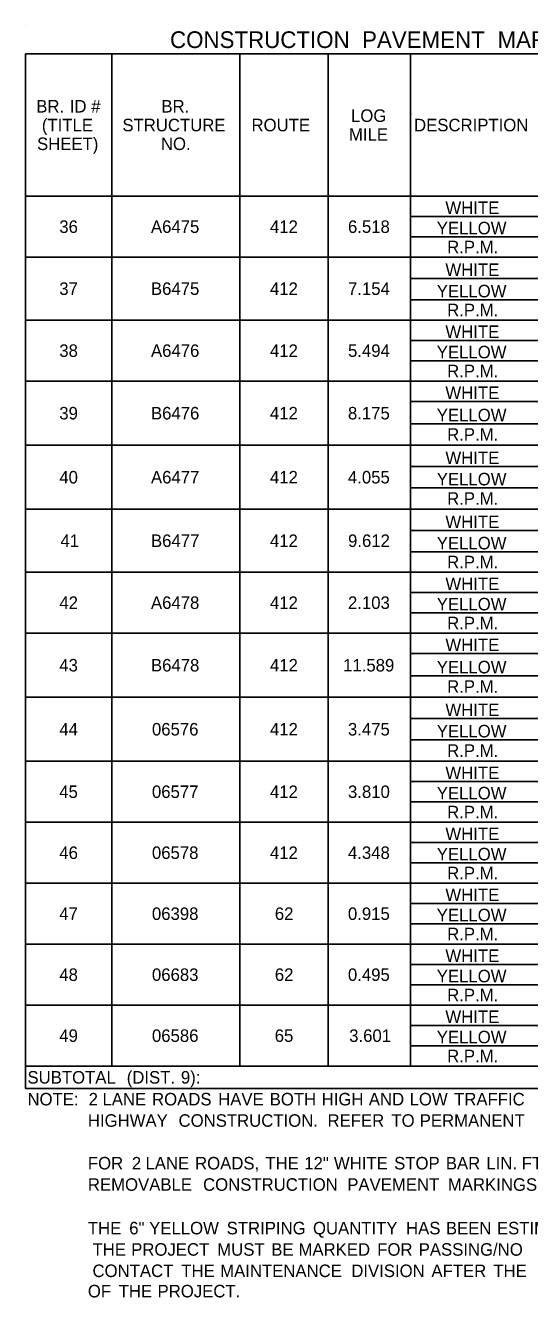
# Model space of a CAD drawing. Extents: x 544420 to 1930787, y -1947044 to 596640.
# Drawn here: x 549970 to 550212, y -1946848 to -1946238 of the extents above; entities that cross this region are included whole.
import ezdxf

# ---------------------------------------------------------------- set-up
doc = ezdxf.new("R2010")
doc.units = 0
doc.layers.add('Default', color=7, linetype='Continuous')

msp = doc.modelspace()

# ---------------------------------------------------------------- linework, layer by layer
at = {"layer": 'Default'}
for p, q in [((549970.43, -1946237.62), (549970.43, -1946237.62)), ((549970.43, -1946251.27), (550672.43, -1946251.27)), ((549970.43, -1946251.27), (550275.6, -1946251.27)), ((549970.43, -1946747.55), (549970.43, -1946251.27)), ((550011.86, -1946736.82), (550011.86, -1946251.27)), ((550073.29, -1946736.82), (550073.29, -1946251.27)), ((550115.7, -1946736.82), (550115.7, -1946251.27)), ((550155.19, -1946736.82), (550155.19, -1946251.27)), ((549970.43, -1946319.52), (550155.19, -1946319.52)), ((549970.43, -1946319.52), (550115.7, -1946319.52)), ((550115.7, -1946319.52), (550672.43, -1946319.52)), ((550155.19, -1946329.27), (550672.43, -1946329.27)), ((550155.19, -1946339.02), (550672.43, -1946339.02)), ((549970.43, -1946348.77), (550672.43, -1946348.77)), ((550155.19, -1946359.01), (550672.43, -1946359.01)), ((550155.19, -1946369.25), (550672.43, -1946369.25)), ((549970.43, -1946379), (550672.43, -1946379)), ((550155.19, -1946388.75), (550672.43, -1946388.75)), ((550155.19, -1946398.5), (550672.43, -1946398.5)), ((549970.43, -1946408.25), (550672.43, -1946408.25)), ((550155.19, -1946418), (550672.43, -1946418)), ((550155.19, -1946428.72), (550672.43, -1946428.72)), ((549970.43, -1946438.96), (550672.43, -1946438.96)), ((550155.19, -1946449.2), (550672.43, -1946449.2)), ((550155.19, -1946459.44), (550672.43, -1946459.44)), ((549970.43, -1946469.67), (550672.43, -1946469.67)), ((550155.19, -1946479.91), (550672.43, -1946479.91)), ((550155.19, -1946490.15), (550672.43, -1946490.15)), ((549970.43, -1946499.9), (550672.43, -1946499.9)), ((550155.19, -1946509.65), (550672.43, -1946509.65)), ((550155.19, -1946519.4), (550672.43, -1946519.4)), ((549970.43, -1946529.15), (550672.43, -1946529.15)), ((550155.19, -1946538.9), (550672.43, -1946538.9)), ((550155.19, -1946549.62), (550672.43, -1946549.62)), ((549970.43, -1946559.86), (550672.43, -1946559.86)), ((550155.19, -1946570.1), (550672.43, -1946570.1)), ((550155.19, -1946580.34), (550672.43, -1946580.34)), ((549970.43, -1946590.57), (550672.43, -1946590.57)), ((550155.19, -1946600.32), (550672.43, -1946600.32)), ((550155.19, -1946610.07), (550672.43, -1946610.07)), ((549970.43, -1946619.82), (550672.43, -1946619.82)), ((550155.19, -1946629.57), (550672.43, -1946629.57)), ((550155.19, -1946639.32), (550672.43, -1946639.32)), ((549970.43, -1946649.07), (550672.43, -1946649.07)), ((550155.19, -1946658.82), (550672.43, -1946658.82)), ((550155.19, -1946668.57), (550672.43, -1946668.57)), ((549970.43, -1946678.32), (550672.43, -1946678.32)), ((550155.19, -1946688.07), (550672.43, -1946688.07)), ((550155.19, -1946697.82), (550672.43, -1946697.82)), ((549970.43, -1946707.57), (550672.43, -1946707.57)), ((550155.19, -1946717.32), (550672.43, -1946717.32)), ((550155.19, -1946727.07), (550672.43, -1946727.07)), ((549970.43, -1946736.82), (550672.43, -1946736.82)), ((549970.43, -1946747.55), (550672.43, -1946747.55))]:
    msp.add_line(p, q, dxfattribs=at)

# ---------------------------------------------------------------- texts
for s, height, p in [('CONSTRUCTION', 8, (550039.78, -1946248.45)), (' PAVEMENT', 8, (550128.93, -1946248.45)), (' MARKINGS', 8, (550193.92, -1946248.45)), ('BR.', 6, (549975.62, -1946279.4)), (' ID', 6, (549989.48, -1946279.4)), (' #', 6, (549999.78, -1946279.4)), ('BR.', 6, (550035.64, -1946279.4)), ('(TITLE', 6, (549978.31, -1946288.4)), ('STRUCTURE', 6, (550016.93, -1946288.4)), ('ROUTE', 6, (550078.87, -1946288.4)), ('LOG', 6, (550126.62, -1946283.9)), ('DESCRIPTION', 6, (550156.86, -1946288.4)), ('MILE', 6, (550125.64, -1946292.9)), ('SHEET)', 6, (549975.99, -1946297.4)), ('NO.', 6, (550035.41, -1946297.4)), ('WHITE', 6, (550171.89, -1946328.07)), ('36', 6, (549986.67, -1946337.15)), ('A6475', 6, (550030.63, -1946337.15)), ('412', 6, (550087.73, -1946337.15)), ('6.518', 6, (550125.15, -1946337.15)), ('YELLOW', 6, (550167.75, -1946337.82)), ('R.P.M.', 6, (550172.73, -1946346.9)), ('WHITE', 6, (550171.89, -1946357.81)), ('37', 6, (549986.67, -1946366.89)), ('B6475', 6, (550030.63, -1946366.89)), ('412', 6, (550087.73, -1946366.89)), ('7.154', 6, (550125.16, -1946366.89)), ('YELLOW', 6, (550167.75, -1946368.05)), ('R.P.M.', 6, (550172.73, -1946377.12)), ('WHITE', 6, (550171.89, -1946387.55)), ('38', 6, (549986.67, -1946396.62)), ('A6476', 6, (550030.65, -1946396.62)), ('412', 6, (550087.73, -1946396.62)), ('5.494', 6, (550125.16, -1946396.62)), ('YELLOW', 6, (550167.75, -1946397.3)), ('R.P.M.', 6, (550172.73, -1946406.37)), ('WHITE', 6, (550171.89, -1946416.8)), ('39', 6, (549986.67, -1946426.61)), ('B6476', 6, (550030.65, -1946426.61)), ('412', 6, (550087.73, -1946426.61)), ('8.175', 6, (550125.13, -1946426.61)), ('YELLOW', 6, (550167.75, -1946427.52)), ('R.P.M.', 6, (550172.73, -1946436.84)), ('WHITE', 6, (550171.89, -1946448)), ('40', 6, (549986.69, -1946457.32)), ('A6477', 6, (550030.65, -1946457.32)), ('412', 6, (550087.73, -1946457.32)), ('4.055', 6, (550125.13, -1946457.32)), ('YELLOW', 6, (550167.75, -1946458.24)), ('R.P.M.', 6, (550172.73, -1946467.56)), ('WHITE', 6, (550171.89, -1946478.71)), ('41', 6, (549987.25, -1946487.79)), ('B6477', 6, (550030.65, -1946487.79)), ('412', 6, (550087.73, -1946487.79)), ('9.612', 6, (550125.18, -1946487.79)), ('YELLOW', 6, (550167.75, -1946488.95)), ('R.P.M.', 6, (550172.73, -1946498.02)), ('WHITE', 6, (550171.89, -1946508.45)), ('42', 6, (549986.71, -1946517.52)), ('A6478', 6, (550030.64, -1946517.52)), ('412', 6, (550087.73, -1946517.52)), ('2.103', 6, (550125.15, -1946517.52)), ('YELLOW', 6, (550167.75, -1946518.2)), ('R.P.M.', 6, (550172.73, -1946527.27)), ('WHITE', 6, (550171.89, -1946537.7)), ('43', 6, (549986.67, -1946547.51)), ('B6478', 6, (550030.64, -1946547.51)), ('412', 6, (550087.73, -1946547.51)), ('11.589', 6, (550122.82, -1946547.51)), ('YELLOW', 6, (550167.75, -1946548.42)), ('R.P.M.', 6, (550172.73, -1946557.74)), ('WHITE', 6, (550171.89, -1946568.9)), ('44', 6, (549986.69, -1946578.22)), ('06576', 6, (550031.12, -1946578.22)), ('412', 6, (550087.73, -1946578.22)), ('3.475', 6, (550125.13, -1946578.22)), ('YELLOW', 6, (550167.75, -1946579.14)), ('R.P.M.', 6, (550172.73, -1946588.46)), ('WHITE', 6, (550171.89, -1946599.12)), ('45', 6, (549986.65, -1946608.2)), ('06577', 6, (550031.12, -1946608.2)), ('412', 6, (550087.73, -1946608.2)), ('3.810', 6, (550125.16, -1946608.2)), ('YELLOW', 6, (550167.75, -1946608.87)), ('R.P.M.', 6, (550172.73, -1946617.95)), ('WHITE', 6, (550171.89, -1946628.37)), ('46', 6, (549986.67, -1946637.45)), ('06578', 6, (550031.11, -1946637.45)), ('412', 6, (550087.73, -1946637.45)), ('4.348', 6, (550125.15, -1946637.45)), ('YELLOW', 6, (550167.75, -1946638.12)), ('R.P.M.', 6, (550172.73, -1946647.2)), ('WHITE', 6, (550171.89, -1946657.62)), ('47', 6, (549986.67, -1946666.7)), ('06398', 6, (550031.11, -1946666.7)), ('62', 6, (550090.06, -1946666.7)), ('0.915', 6, (550125.13, -1946666.7)), ('YELLOW', 6, (550167.75, -1946667.37)), ('R.P.M.', 6, (550172.73, -1946676.45)), ('WHITE', 6, (550171.89, -1946686.87)), ('48', 6, (549986.67, -1946695.95)), ('06683', 6, (550031.12, -1946695.95)), ('62', 6, (550090.06, -1946695.95)), ('0.495', 6, (550125.13, -1946695.95)), ('YELLOW', 6, (550167.75, -1946696.62)), ('R.P.M.', 6, (550172.73, -1946705.7)), ('WHITE', 6, (550171.89, -1946716.12)), ('49', 6, (549986.67, -1946725.2)), ('06586', 6, (550031.12, -1946725.2)), ('65', 6, (550090, -1946725.2)), ('3.601', 6, (550125.73, -1946725.2)), ('YELLOW', 6, (550167.75, -1946725.87)), ('R.P.M.', 6, (550172.73, -1946734.95)), ('SUBTOTAL', 6, (549971.4, -1946745.19)), (' (DIST.', 6, (550016.79, -1946745.19)), (' 9):', 6, (550042.76, -1946745.19)), ('NOTE:', 6, (549971.4, -1946755.67)), ('  2', 6, (549996.29, -1946755.67)), (' LANE', 6, (550005.16, -1946755.67)), (' ROADS', 6, (550028.94, -1946755.67)), (' HAVE', 6, (550060.65, -1946755.67)), (' BOTH', 6, (550085.36, -1946755.67)), (' HIGH', 6, (550110.3, -1946755.67)), (' AND', 6, (550132.91, -1946755.67)), (' LOW', 6, (550152.49, -1946755.67)), (' TRAFFIC', 6, (550173.82, -1946755.67)), ('             HIGHWAY', 6, (549971.4, -1946765.91)), (' CONSTRUCTION.', 6, (550041.65, -1946765.91)), (' REFER', 6, (550113.11, -1946765.91)), (' TO', 6, (550143.75, -1946765.91)), (' PERMANENT', 6, (550157.34, -1946765.91)), ('             FOR', 6, (549971.4, -1946786.38)), (' 2', 6, (550019.25, -1946786.38)), (' LANE', 6, (550025.79, -1946786.38)), (' ROADS,', 6, (550049.57, -1946786.38)), (' THE', 6, (550083.3, -1946786.38)), (' 12"', 6, (550101.95, -1946786.38)), (' WHITE', 6, (550116.18, -1946786.38)), (' STOP', 6, (550145.07, -1946786.38)), (' BAR', 6, (550169.86, -1946786.38)), (' LIN.', 6, (550189.31, -1946786.38)), (' FT.', 6, (550206.28, -1946786.38)), ('             REMOVABLE', 6, (549971.4, -1946796.62)), (' CONSTRUCTION', 6, (550053.4, -1946796.62)), (' PAVEMENT', 6, (550122.58, -1946796.62)), (' MARKINGS', 6, (550170.86, -1946796.62)), ('             THE', 6, (549971.4, -1946817.52)), (' 6"', 6, (550017.98, -1946817.52)), (' YELLOW', 6, (550027.55, -1946817.52)), (' STRIPING', 6, (550064.73, -1946817.52)), (' QUANTITY', 6, (550106.12, -1946817.52)), (' HAS', 6, (550150.77, -1946817.52)), (' BEEN', 6, (550169.9, -1946817.52)), (' ESTIMATED', 6, (550194.38, -1946817.52)), ('THE', 6, (550002.6, -1946827.76)), (' PROJECT', 6, (550018.92, -1946827.76)), (' MUST', 6, (550060.21, -1946827.76)), (' BE', 6, (550086.12, -1946827.76)), (' MARKED', 6, (550099.19, -1946827.76)), (' FOR', 6, (550136.94, -1946827.76)), (' PASSING/NO', 6, (550156.85, -1946827.76)), ('CONTACT', 6, (550002.6, -1946838)), (' THE', 6, (550042.95, -1946838)), (' MAINTENANCE', 6, (550061.6, -1946838)), (' DIVISION', 6, (550124.51, -1946838)), (' AFTER', 6, (550162.95, -1946838)), (' THE', 6, (550192.65, -1946838)), ('             OF', 6, (549971.4, -1946847.75)), (' THE', 6, (550012.92, -1946847.75)), (' PROJECT.', 6, (550031.57, -1946847.75))]:
    msp.add_text(s, height=height, dxfattribs=at).set_placement(p)

doc.saveas('drawing.dxf')
